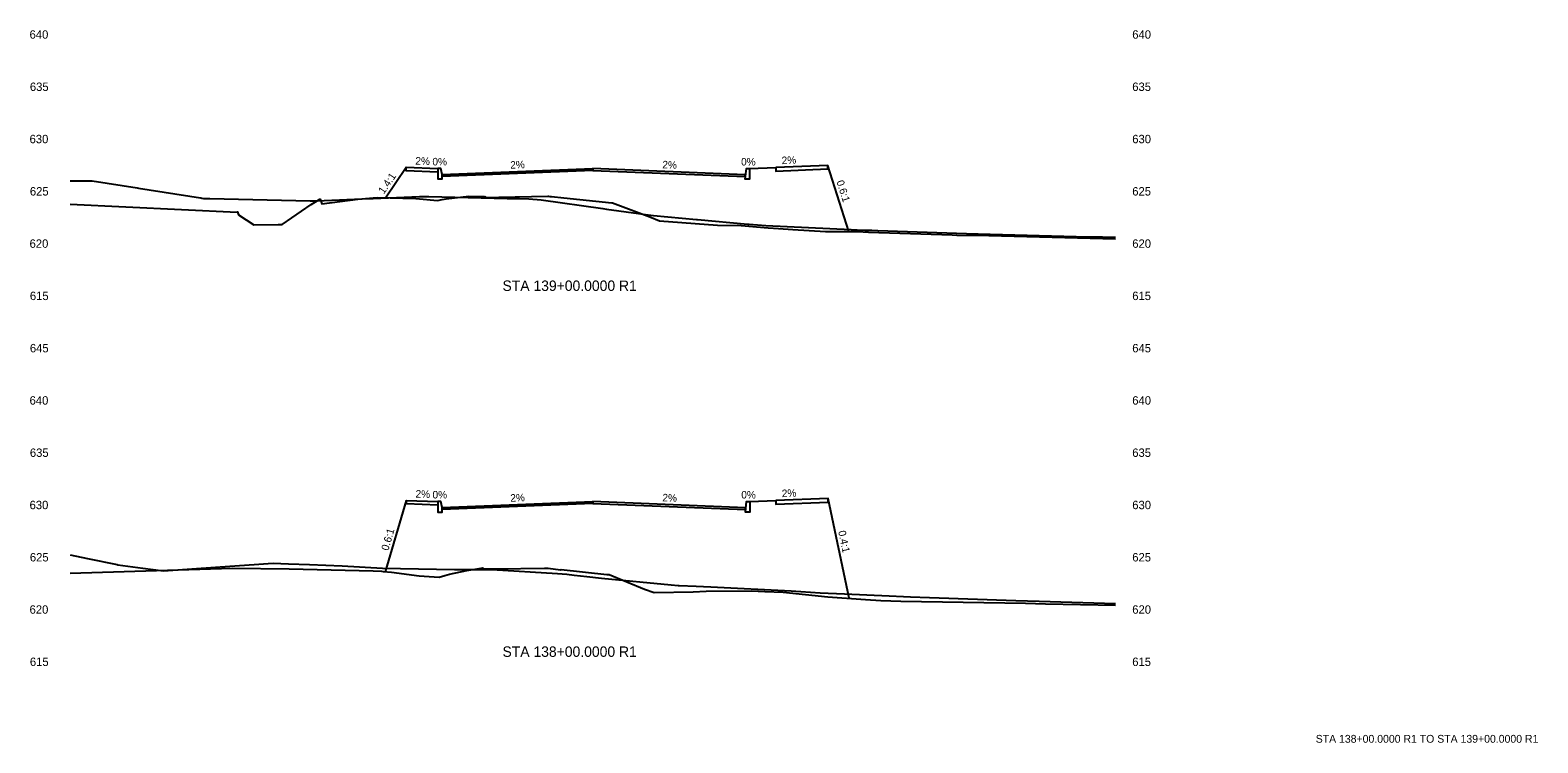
# Model space of a CAD drawing. Extents: x 12 to 301, y 16 to 1707.
# Drawn here: x 12.4 to 300.8, y 240.9 to 377.2 of the extents above; entities that cross this region are included whole.
import ezdxf

# ---------------------------------------------------------------- set-up
doc = ezdxf.new("R2010")
doc.units = 0
for name, color, linetype in [('BORD_text_large_2', 7, 'Continuous'), ('Default', 7, 'Continuous'), ('Draft_XS_Point_Label_Indicator', 7, 'Continuous'), ('Draft_XS_Text', 7, 'Continuous'), ('Grade_Veg_Grass', 7, 'Continuous'), ('P_XS_Sections', 7, 'Continuous'), ('Road_Curb', 7, 'Continuous'), ('Road_Pave_Asphalt', 7, 'Continuous'), ('Road_Sidewalk', 7, 'Continuous'), ('Terrain_Exterior', 7, 'Continuous')]:
    doc.layers.add(name, color=color, linetype=linetype)

msp = doc.modelspace()

# ---------------------------------------------------------------- linework, layer by layer
at = {"layer": 'Default'}
for points in [[(20, 343.96), (51.98, 342.4), (52.03, 342.49), (52.26, 341.91), (55.14, 339.99), (59.84, 340.08), (60.6, 340.08), (66.16, 343.86), (67.79, 344.93), (67.87, 344.91), (68.17, 344.04), (75.09, 344.92), (78.78, 345.2), (86.13, 345), (90.32, 344.67), (91.18, 344.84), (91.96, 344.97), (96.3, 345.46), (99.21, 345.44), (99.27, 345.39), (99.62, 345.25), (102.06, 345.29), (111.42, 345.47), (111.56, 345.46), (111.82, 345.41), (112.11, 345.41), (114.47, 345.16), (123.66, 344.2), (123.78, 344.2), (130.92, 341.52), (132.79, 340.74), (143.9, 339.92), (148.39, 339.85), (153.55, 339.43), (155.55, 339.29), (158.3, 339.13), (164.52, 338.73), (170.7, 338.74), (172.74, 338.61), (188.78, 338.09), (189.63, 338.04), (195.76, 337.94), (220, 337.32)], [(20, 273.33), (51.01, 274.31), (61.92, 274.18), (78.01, 273.81), (79.6, 273.76), (79.94, 273.66), (81.48, 273.54), (86.82, 272.82), (90.64, 272.58), (91.71, 272.92), (92.57, 273.19), (95.91, 273.87), (98.95, 274.37), (99.18, 274.2), (99.27, 274.17), (101.66, 274.17), (110.8, 274.33), (111.1, 274.31), (111.17, 274.3), (111.25, 274.3), (111.47, 274.3), (113.84, 274.02), (113.98, 274.05), (122.7, 273.12), (123.14, 273.12), (129.93, 270.29), (131.74, 269.69), (139.23, 269.81), (141.73, 269.91), (150.36, 270), (152.94, 269.82), (156.41, 269.73), (164.99, 268.8), (172.17, 268.35), (175.15, 268.14), (178.96, 267.99), (202.79, 267.59), (206.64, 267.51), (220, 267.25)]]:
    msp.add_lwpolyline(points, dxfattribs=at)
at = {"layer": 'Grade_Veg_Grass'}
for points in [[(80.34, 345.16), (80.34, 345.16), (84.34, 351)], [(150.01, 350.74), (155.01, 350.94)], [(169.01, 338.74), (169.01, 338.74), (165.01, 351.34)], [(80.37, 273.63), (80.37, 273.63), (84.37, 287.29)], [(150.03, 287.04), (155.03, 287.24)], [(169.03, 268.55), (169.03, 268.55), (165.03, 287.64)]]:
    msp.add_lwpolyline(points, dxfattribs=at)
at = {"layer": 'Road_Curb'}
for points in [[(90.34, 350.76), (90.34, 348.76), (91.17, 348.76), (91.17, 349.59), (90.94, 350.76), (90.34, 350.76)], [(150.01, 350.74), (150.01, 348.74), (149.17, 348.74), (149.4, 350.74), (150.01, 350.74)], [(90.37, 287.05), (90.37, 285.05), (91.2, 285.05), (91.2, 285.89), (90.97, 287.05), (90.37, 287.05)], [(150.03, 287.04), (150.03, 285.04), (149.2, 285.04), (149.43, 287.04), (150.03, 287.04)]]:
    msp.add_lwpolyline(points, dxfattribs=at)
at = {"layer": 'Road_Pave_Asphalt'}
for points in [[(91.17, 349.59), (120, 350.74), (120, 350.41), (120, 350.41), (91.17, 349.26), (91.17, 349.26), (91.17, 349.26), (91.17, 349.59), (91.17, 349.59)], [(149.17, 349.58), (120, 350.74), (120, 350.41), (120, 350.41), (149.17, 349.24), (149.17, 349.24), (149.17, 349.24), (149.17, 349.58), (149.17, 349.58)], [(91.2, 285.89), (120, 287.04), (120, 286.71), (120, 286.71), (91.2, 285.55), (91.2, 285.55), (91.2, 285.55), (91.2, 285.89), (91.2, 285.89)], [(149.2, 285.87), (120, 287.04), (120, 286.71), (120, 286.71), (149.2, 285.54), (149.2, 285.54), (149.2, 285.54), (149.2, 285.87), (149.2, 285.87)]]:
    msp.add_lwpolyline(points, dxfattribs=at)
at = {"layer": 'Road_Sidewalk'}
for points in [[(90.34, 350.76), (90.34, 350.09), (84.34, 350.33), (84.34, 351), (90.34, 350.76)], [(155.01, 350.94), (155.01, 350.28), (165.01, 350.68), (165.01, 351.34), (155.01, 350.94)], [(90.37, 287.05), (90.37, 286.39), (84.37, 286.63), (84.37, 287.29), (90.37, 287.05)], [(155.03, 287.24), (155.03, 286.57), (165.03, 286.97), (165.03, 287.64), (155.03, 287.24)]]:
    msp.add_lwpolyline(points, dxfattribs=at)
at = {"layer": 'Terrain_Exterior'}
for points in [[(20, 348.42), (24.07, 348.4), (24.18, 348.4), (24.23, 348.4), (32.84, 347.04), (33.13, 347), (44.95, 345.14), (45, 345.13), (45.19, 345.1), (45.53, 345.05), (45.71, 345.02), (46.78, 345), (65.94, 344.6), (67.18, 344.56), (77.35, 345), (77.98, 345.03), (86.87, 345.41), (88.66, 345.42), (103.61, 345.06), (105.96, 345), (107.8, 344.95), (110.14, 344.76), (121.93, 343.1), (122.62, 343), (128.74, 342.14), (129.56, 342.04), (131.61, 341.78), (139.85, 341.02), (140.03, 341), (149.67, 340.11), (149.93, 340.09), (153.09, 339.87), (169.43, 339.11), (170.6, 339.06), (172.06, 339), (173.39, 338.95), (174.57, 338.9), (191.54, 338.35), (196.04, 338.21), (212.47, 337.79), (217.52, 337.67), (220, 337.62)], [(20, 276.88), (23.37, 276.18), (29.04, 275), (29.13, 274.98), (33.9, 274.33), (37.91, 273.79), (47.82, 274.48), (50.6, 274.67), (55.21, 275), (57.89, 275.19), (58.85, 275.26), (61.83, 275.15), (65.82, 275), (72.08, 274.77), (79.78, 274.29), (93.56, 274.09), (100.71, 274.09), (113.29, 273.27), (115.03, 273.16), (116.42, 273), (118.9, 272.71), (121.65, 272.4), (135, 271.13), (136.36, 271), (136.51, 270.99), (139.8, 270.87), (142.58, 270.76), (157.99, 269.99), (163.51, 269.62), (168.2, 269.4), (176.74, 269), (179.46, 268.87), (180.78, 268.82), (184.45, 268.69), (200.94, 268.13), (205.38, 267.99), (220, 267.57)]]:
    msp.add_lwpolyline(points, dxfattribs=at)

# ---------------------------------------------------------------- texts
at = {"layer": 'BORD_text_large_2'}
msp.add_text('STA 138+00.0000 R1 TO STA 139+00.0000 R1', height=1.5, dxfattribs=at).set_placement((258.32, 240.92))
at = {"layer": 'Draft_XS_Point_Label_Indicator'}
for p in [(84.33, 350.99), (90.33, 350.75), (90.93, 350.75), (91.16, 349.58), (119.99, 350.73), (119.99, 350.73), (149.16, 349.57), (149.39, 350.73), (150, 350.73), (155, 350.93), (165, 351.33), (80.33, 345.15), (169, 338.72), (84.36, 287.28), (90.36, 287.04), (90.96, 287.04), (91.19, 285.88), (119.99, 287.03), (119.99, 287.03), (149.19, 285.86), (149.42, 287.03), (150.02, 287.03), (155.02, 287.23), (165.02, 287.63), (80.36, 273.61), (169.02, 268.54)]:
    msp.add_text('X', height=0.024, dxfattribs=at).set_placement(p)
at = {"layer": 'Draft_XS_Text'}
for s, height, p in [('640', 1.608, (12.26, 375.6)), ('640', 1.608, (223.22, 375.6)), ('635', 1.608, (12.32, 365.6)), ('635', 1.608, (223.22, 365.6)), ('630', 1.608, (12.26, 355.6)), ('630', 1.608, (223.22, 355.6)), ('625', 1.608, (12.32, 345.6)), ('625', 1.608, (223.22, 345.6)), ('620', 1.608, (12.26, 335.6)), ('620', 1.608, (223.22, 335.6)), ('STA 139+00.0000 R1', 1.992, (102.74, 327.35)), ('615', 1.608, (12.32, 325.6)), ('615', 1.608, (223.22, 325.6)), ('645', 1.608, (12.32, 315.6)), ('645', 1.608, (223.22, 315.6)), ('640', 1.608, (12.26, 305.6)), ('640', 1.608, (223.22, 305.6)), ('635', 1.608, (12.32, 295.6)), ('635', 1.608, (223.22, 295.6)), ('630', 1.608, (12.26, 285.6)), ('630', 1.608, (223.22, 285.6)), ('625', 1.608, (12.32, 275.6)), ('625', 1.608, (223.22, 275.6)), ('620', 1.608, (12.26, 265.6)), ('620', 1.608, (223.22, 265.6)), ('615', 1.608, (12.32, 255.6)), ('STA 138+00.0000 R1', 1.992, (102.74, 257.35)), ('615', 1.608, (223.22, 255.6))]:
    msp.add_text(s, height=height, dxfattribs=at).set_placement(p)
for s, rotation, p in [('2%', 357.7094, (86.05, 351.53)), ('2%', 357.7094, (86.05, 351.53)), ('2%', 357.7094, (86.05, 351.53)), ('0%', 360, (89.33, 351.36)), ('0%', 360, (89.33, 351.36)), ('0%', 360, (89.33, 351.36)), ('2%', 2.2906, (104.25, 350.72)), ('2%', 2.2906, (104.25, 350.72)), ('2%', 2.2906, (104.25, 350.72)), ('2%', 357.7094, (133.3, 350.81)), ('2%', 357.7094, (133.3, 350.81)), ('2%', 357.7094, (133.3, 350.81)), ('0%', 0, (148.39, 351.34)), ('0%', 0, (148.39, 351.34)), ('0%', 0, (148.39, 351.34)), ('2%', 2.2906, (156.17, 351.59)), ('2%', 2.2906, (156.17, 351.59)), ('2%', 2.2906, (156.17, 351.59)), ('1.4:1', 55.5871, (80.04, 345.78)), ('1.4:1', 55.5871, (80.04, 345.78)), ('1.4:1', 55.5871, (80.04, 345.78)), ('0.6:1', 287.6005, (166.61, 348.27)), ('0.6:1', 287.6005, (166.61, 348.27)), ('0.6:1', 287.6005, (166.61, 348.27)), ('2%', 357.7094, (86.08, 287.83)), ('2%', 357.7094, (86.08, 287.83)), ('2%', 357.7094, (86.08, 287.83)), ('0%', 360, (89.35, 287.65)), ('0%', 360, (89.35, 287.65)), ('0%', 360, (89.35, 287.65)), ('2%', 2.2906, (104.26, 287.01)), ('2%', 2.2906, (104.26, 287.01)), ('2%', 2.2906, (104.26, 287.01)), ('2%', 357.7094, (133.31, 287.11)), ('2%', 357.7094, (133.31, 287.11)), ('2%', 357.7094, (133.31, 287.11)), ('0%', 360, (148.42, 287.64)), ('0%', 360, (148.42, 287.64)), ('0%', 360, (148.42, 287.64)), ('2%', 2.2906, (156.2, 287.89)), ('2%', 2.2906, (156.2, 287.89)), ('2%', 2.2906, (156.2, 287.89)), ('0.6:1', 73.6876, (80.89, 277.56)), ('0.6:1', 73.6876, (80.89, 277.56)), ('0.6:1', 73.6876, (80.89, 277.56)), ('0.4:1', 281.8332, (166.96, 281.35)), ('0.4:1', 281.8332, (166.96, 281.35)), ('0.4:1', 281.8332, (166.96, 281.35))]:
    msp.add_text(s, height=1.44, rotation=rotation, dxfattribs=at).set_placement(p)
at = {"layer": 'P_XS_Sections'}
for p in [(20, 325), (20, 255)]:
    msp.add_text('-', height=0.0001, dxfattribs=at).set_placement(p)

doc.saveas('drawing.dxf')
